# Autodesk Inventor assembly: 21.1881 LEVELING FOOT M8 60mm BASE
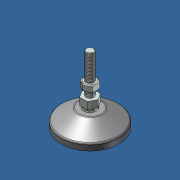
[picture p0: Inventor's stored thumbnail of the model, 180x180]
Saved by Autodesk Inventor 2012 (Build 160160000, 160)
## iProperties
Created: 2007-03
Part Number: 21.1881 LEVELING FOOT M8 60mm BASE
Document SubType Name: Assembly
Designer: Andy Moles
Mass: 84.2698 g
Surface Area: 169.24 cm^2
Volume: 43.6824 cm^3
Density: 1.92915 g/cm^3
Author: Andy Moles
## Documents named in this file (5)
- C:\Andys Backup Data\ANDY'S INVENTOR\INVENTOR LIBRARIES\PARTS LIBRARY\FEET WHEELS FLOOR FASTENING SUPPORTS\21.1881 LEVELING FOOT M8 60mm BASE.iam
- C:\Andys Backup Data\ANDY'S INVENTOR\INVENTOR LIBRARIES\PARTS LIBRARY\FEET WHEELS FLOOR FASTENING SUPPORTS\SUBCOMPONENTS\LEVELING FEET SUBCOMPONENTS\THREADED STUD 8mm.ipt
- C:\Andys Backup Data\ANDY'S INVENTOR\INVENTOR LIBRARIES\PARTS LIBRARY\FASTENING ELEMENTS\NUTS\21.1526 M8 HEX NUT.ipt
- C:\Andys Backup Data\ANDY'S INVENTOR\INVENTOR LIBRARIES\PARTS LIBRARY\FEET WHEELS FLOOR FASTENING SUPPORTS\SUBCOMPONENTS\LEVELING FEET SUBCOMPONENTS\PAD 60mm PLASTIC.ipt
- C:\Andys Backup Data\ANDY'S INVENTOR\INVENTOR LIBRARIES\PARTS LIBRARY\FEET WHEELS FLOOR FASTENING SUPPORTS\SUBCOMPONENTS\LEVELING FEET SUBCOMPONENTS\ANTI-SKID PAD 60mm.ipt
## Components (4 placed, 4 different names)
1. ANTI-SKID PAD 60mm:1 — Insert:1
2. PAD 60mm PLASTIC:1 — Insert:1, Tangent:1, Mate:1
3. THREADED STUD 8mm:1 — Tangent:1, Mate:1, Mate:2
4. 21.1526 M8 HEX NUT:1 — Mate:2
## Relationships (4: Mate 2, Insert 1, Tangent 1)
- Insert:1: ANTI-SKID PAD 60mm:1 ↔ PAD 60mm PLASTIC:1
- Tangent:1: PAD 60mm PLASTIC:1 ↔ THREADED STUD 8mm:1
- Mate:1: PAD 60mm PLASTIC:1 ↔ THREADED STUD 8mm:1
- Mate:2: THREADED STUD 8mm:1 ↔ 21.1526 M8 HEX NUT:1
